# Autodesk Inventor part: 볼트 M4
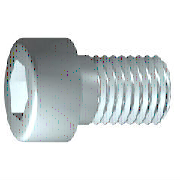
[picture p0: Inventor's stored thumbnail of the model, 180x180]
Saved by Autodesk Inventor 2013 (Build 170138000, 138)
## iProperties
IsCustomPart: 0
Created: 2012-02
Part Number: 볼트 M4
Material: 스테인리스강
Description: 6각 소켓 머리 캡 나사
Document SubType Name: Modeling
Standard: ISO 4762
Designer: mduedu
Standard Revision: Fourth edition 2004-03-01
Standards Organization: ISO
Language: ko-KR
Size Designation: M4 x 12
Categories: <MemberInstance><Categories><Category DisplayName="조임쇠" InternalName="e4da775c-781d-43d5-af7c-5136215cf5a6" Mnemonic="FSTN"><Category DisplayName="볼트" InternalN
Density: 7.75 g/cm^3
Author: mduedu
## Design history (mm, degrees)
sketch "스케치1"
  geometry: L1 (-1, 0)-(12, 0); L2 (12, 0)-(12, 2); L3 (12, 2)-(1.75, 2); L4 (1.75, 2)-(1.32, 2); L5 (1.32, 2)-(0, 2); L6 (0, 2)-(0, 3.5); L7 (0, 3.5)-(-4, 3.5); L8 (-4, 3.5)-(-4, 1.732); L9 (-4, 1.732)-(-2, 1.732); L10 (-2, 1.732)-(-1, 0); L11 (-7.2, 0)-(15.2, 0) reference; L12 (0, -0.7)-(0, 4.2) reference; L13 (1.75, 2)-(0, 2)
  constraints: 22 end point, 6 parallel, 2 collinear, 2 perpendicular, 1 horizontal, 1 point on line
  dimensions: "d1" = 10.25 distance from line of L3.end L2 (= GEL); "d2" = 0.42952 distance of L4.end L3.end (computed from GAL); "d3" = 4 distance between parallel lines of L8 L6 (= KOH); "d4" = 2 distance of L8.end L9.end (= INTI); "d5" = 60 deg angle of L10 L1; "d6" = 4 diameter of L3 L1 (= GD); "d7" = 4 diameter of L5 L1 (= BDM); "d8" = 3.4641 diameter of L9 L1 (= 1.1547 x SW); "d9" = 7 diameter of L7 L1 (= KOD); "d26" = 12 distance between parallel lines of L12 L2 (= NLG)
revolve "본체" sketch "스케치1" stored, may be unused: angle "d10" = 90 deg
sketch "스케치2"
  geometry: L1 (0, -4.9)-(0, 4.9) reference; L2 (-4.9, 0)-(4.9, 0) reference; L3 (1.732, 0)-(0.866, -1.5); L4 (0.866, -1.5)-(-0.866, -1.5); L5 (-0.866, -1.5)-(-1.732, 0); L6 (-1.732, 0)-(-0.866, 1.5); L7 (-0.866, 1.5)-(0.866, 1.5); L8 (0.866, 1.5)-(1.732, 0); 2 further points
  constraints: 12 end point, 1 coincident, 1 horizontal alignment, 1 point on line, 12 other
extrude "슬롯" join sketch "스케치2" stored distance "d11" = 10; taper "d12" = 0 deg
workplane "Work Plane1"
fillet "Fillet2" dims "d30" = 0.1 (= R)
body "Solid1"
fillet "모깎기1" dims "d17" = 0.4 (= RR)
feature "스레드" dims "d13" = 10.25 (= GEL), "d14" = 0
chamfer "모따기1" distance "d15" = 0.42941 (= -0.5 x SPD + 0.5 x GD); stored, may be unused: second distance "d16" = 0.42941 (= GUL), angle "d27" = 45 deg
other parameters: "GD" = 4 [user parameter; used in 2 equation terms], "NLG" = 12 [user parameter; used in 1 equation term], "GEL" = 10.25 [user parameter; used in 2 equation terms], "KOD" = 7 [user parameter; used in 1 equation term], "KOH" = 4 [user parameter; used in 1 equation term], "INTI" = 2 [user parameter; used in 1 equation term], "GAL" = 0.42941 (= 0.61345 x PTC) [user parameter; used in 1 equation term], "GUL" = 0.42941 (= 0.61345 x PTC) [user parameter; used in 1 equation term], "BDM" = 4 (= NND) [user parameter; used in 1 equation term], "SW" = 3 [user parameter; used in 2 equation terms], "RR" = 0.4 [user parameter; used in 1 equation term], "SPD" = 3.14117 (= NND - 1.2269 x PTC) [user parameter; used in 1 equation term], "d19" = 0, "d28" = 0, "d29" = 0, "R" = 0.1 [user parameter; used in 1 equation term], "TOA" = 30 deg [user parameter], "GD1" = 3.14117 (= THREADDIA - 1.2269 x PTC) [user parameter], "THREADDIA" = 4 [user parameter; used in 1 equation term], "FAWI" = 45 deg [user parameter], "TPU" = 14.28571 (computed from PTC) [user parameter], "PTC" = 0.7 [user parameter; used in 5 equation terms], "NND" = 4 [user parameter; used in 2 equation terms], "E0" = 3.465 (= 1.155 x SW) [user parameter]
